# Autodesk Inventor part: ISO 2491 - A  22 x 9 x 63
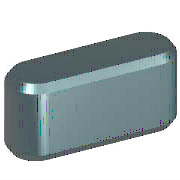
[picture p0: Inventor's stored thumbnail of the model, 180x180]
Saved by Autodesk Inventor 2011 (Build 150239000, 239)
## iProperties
IsCustomPart: 0
Created: 2010-02
Part Number: ISO 2491 - A  22 x 9 x 63
Material: Steel, Mild
Description: Thin parallel keys
Document SubType Name: Modeling
Standard: ISO 2491
Designer: HTYCOON
Standard Revision: First edition 1974-08-15
Standards Organization: ISO
Language: en-US
Size Designation: A  22 x 9 x 63
Categories: <MemberInstance><Categories><Category DisplayName="Shaft Parts" InternalName="7f7aeb1f-a693-4053-b835-cee3144e0d98" Mnemonic="SHFT"><Category DisplayName="Keys"
Density: 1 g/cm^3
Author: HTYCOON
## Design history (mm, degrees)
sketch "Sketch1"
  geometry: L1 (11, 11)-(52, 11); L2 (52, -11)-(11, -11); L3 (0, 9.4)-(0, -7.4) reference; L4 (-5, 0)-(30, 0) reference; L5 (63, 0)-(63, 7); A1 r 11 centre (11, 0) between (11, 11) and (11, -11); A2 r 11 centre (52, 0) between (52, -11) and (52, 11)
  constraints: 6 end point, 5 point on circle, 4 tangent, 3 point on line, 2 centre point, 1 horizontal, 1 parallel, 1 perpendicular
  dimensions: "d0" = 11 radius of A1 (= 0.5 x PB); "d13" = 11 radius of A2 (= 0.5 x PB); "d14" = 63 distance between parallel lines of L5 L3 (= NLG)
extrude "Body1" new body sketch "Sketch1" taper "d3" = 0 deg; stored distance "d4" = 10
workplane "Work Plane3"
body "Solid1"
workplane "Work Plane1"
workplane "Work Plane2"
chamfer "Chamfer1" distance "d8" = 0.8 (= PHH); stored, may be unused: second distance "d9" = 0.8 (= PHH), angle "d15" = 45 deg
other parameters: "d1" = -5.5 (= -PNT), "d2" = 3.5 (= PH - PNT), "NLG" = 63 [user parameter; used in 1 equation term], "PB" = 22 [user parameter; used in 2 equation terms], "PNT" = 5.5 [user parameter; used in 2 equation terms], "PH" = 9 [user parameter; used in 1 equation term], "PHH" = 0.8 [user parameter; used in 2 equation terms], "d10" = 0, "d16" = 0, "d17" = 0, "d18" = 0, "RR" = 0.4 [user parameter], "WDMIN" = 75 [user parameter], "WDMAX" = 85 [user parameter], "PLB1" = 63 [user parameter], "PLB2" = 63 [user parameter], "PUEB" = 3.8 [user parameter]
